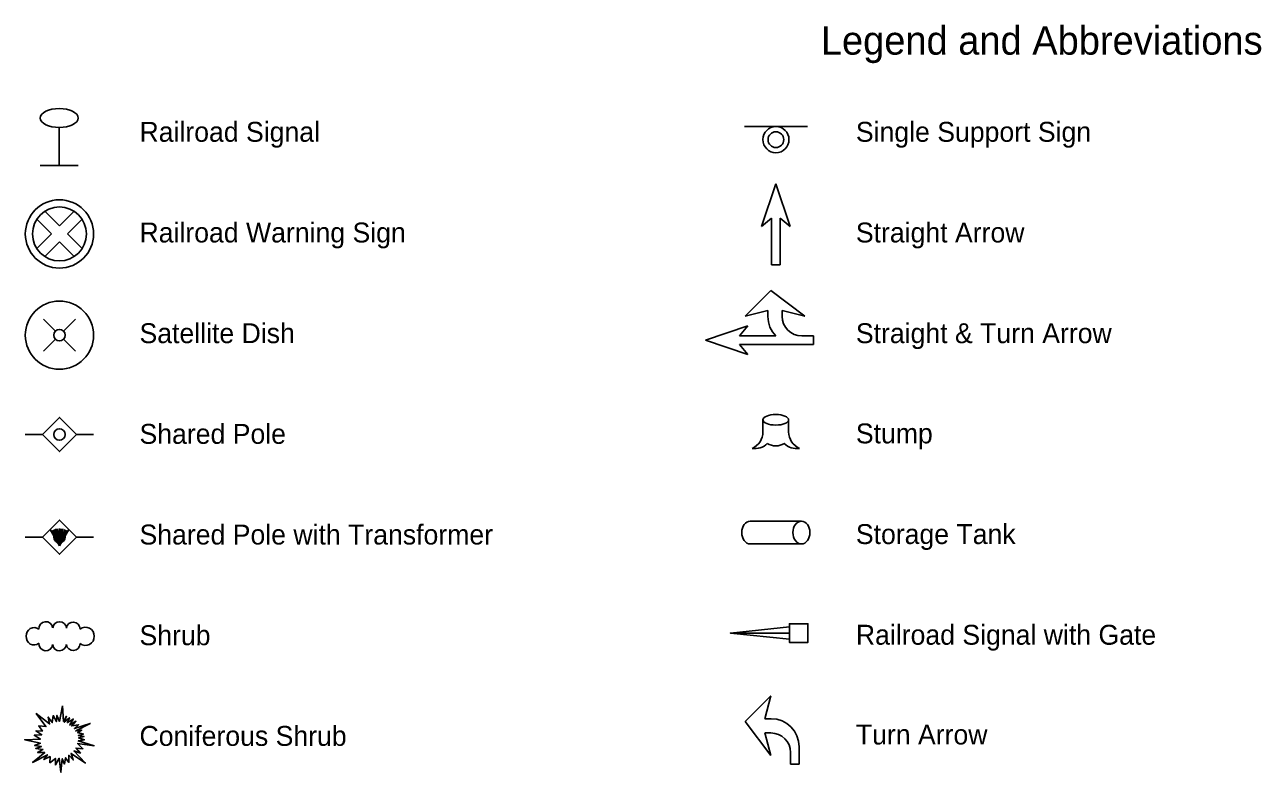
# Model space of a CAD drawing. Extents: x -371 to 730, y -9 to 425.
# Drawn here: x -68.8 to 40, y 358.9 to 424.6 of the extents above; entities that cross this region are included whole.
import ezdxf

# ---------------------------------------------------------------- set-up
doc = ezdxf.new("R2010")
doc.units = 0
for name, color, linetype in [('Pavemk_ep', 7, 'Continuous'), ('PolePower_ep', 7, 'Continuous'), ('RailroadMisc_ep', 7, 'Continuous'), ('SateDish_ep', 7, 'Continuous'), ('Shrub_ep', 7, 'Continuous'), ('SignSingle_ep', 7, 'Continuous'), ('Stump_ep', 7, 'Continuous'), ('TankStor_ep', 7, 'Continuous')]:
    doc.layers.add(name, color=color, linetype=linetype)

# ---------------------------------------------------------------- blocks, each defined once
blk = doc.blocks.new('STAROW')
at = {"layer": 'Pavemk_ep'}
for p, q in [((-1.67, -5), (0, 0)), ((0, 0), (1.67, -5)), ((-0.5, -4), (-1.67, -5)), ((-0.5, -9.5), (-0.5, -4)), ((0.5, -9.5), (0.5, -4)), ((1.67, -5), (0.5, -4)), ((-0.5, -9.5), (0.5, -9.5))]:
    blk.add_line(p, q, dxfattribs=at)
blk = doc.blocks.new('STATRN')
at = {"layer": 'Pavemk_ep'}
for p, q in [((-0.59, 5.33), (-3.59, 2.33)), ((-0.59, 5.33), (3.41, 2.33)), ((-3.59, 2.33), (-0.92, 3)), ((-0.92, 3), (-0.92, 2.28)), ((0.75, 3), (0.75, 2.3)), ((3.41, 2.33), (0.75, 3)), ((-3.26, 1.17), (-8.26, -0.5)), ((-4.26, 0), (-3.26, 1.17)), ((0, 0), (-4.26, 0)), ((4.41, 0), (3.04, 0)), ((4.41, 0), (4.41, -1)), ((-8.26, -0.5), (-3.26, -2.17)), ((4.41, -1), (-4.26, -1)), ((-3.26, -2.17), (-4.26, -1))]:
    blk.add_line(p, q, dxfattribs=at)
for centre, radius, end in [((2.36, 2.28), 3.28, 224.0462), ((3.04, 2.3), 2.3, 270)]:
    blk.add_arc(centre, radius, 180, end, dxfattribs=at)
blk = doc.blocks.new('TA')
at = {"layer": 'Pavemk_ep'}
for p, q in [((0, 0), (3, 3)), ((3, 3), (2.33, 0.33)), ((0, 0), (3, -4)), ((2.33, 0.33), (3.05175, 0.33)), ((2.33, -1.34), (3.03608, -1.34)), ((3, -4), (2.33, -1.34)), ((5.333, -5), (5.333, -3.63692)), ((6.333, -5), (6.333, -2.95125)), ((5.333, -5), (6.333, -5))]:
    blk.add_line(p, q, dxfattribs=at)
for centre, radius in [((3.05175, -2.95125), 3.28125), ((3.03608, -3.63692), 2.29692)]:
    blk.add_arc(centre, radius, 0, 90, dxfattribs=at)

msp = doc.modelspace()

# ---------------------------------------------------------------- linework, layer by layer
at = {"layer": 'PolePower_ep'}
for p, q in [((-68.71, 388.57), (-67.21, 388.57)), ((-64.21, 388.57), (-62.71, 388.57)), ((-68.71, 379.55), (-67.21, 379.55)), ((-65.71, 378.79), (-66.53, 380.23)), ((-66.32, 380.17), (-65.71, 378.79)), ((-66.17, 380.23), (-65.71, 378.79)), ((-66.02, 380.27), (-65.71, 378.79)), ((-65.87, 380.29), (-65.71, 378.79)), ((-65.71, 380.3), (-65.71, 378.79)), ((-65.55, 380.29), (-65.71, 378.79)), ((-65.4, 380.27), (-65.71, 378.79)), ((-64.88, 380.23), (-65.71, 378.79)), ((-65.24, 380.23), (-65.71, 378.79)), ((-65.1, 380.17), (-65.71, 378.79)), ((-64.21, 379.55), (-62.71, 379.55))]:
    msp.add_line(p, q, dxfattribs=at)
for points in [[(-67.21, 388.57), (-65.71, 387.07), (-64.21, 388.57), (-65.71, 390.07)], [(-67.21, 379.55), (-65.71, 378.05), (-64.21, 379.55), (-65.71, 381.05)]]:
    msp.add_lwpolyline(points, close=True, dxfattribs=at)
for centre in [(-65.71, 388.57), (-65.71, 379.55)]:
    msp.add_circle(centre, 0.5, dxfattribs=at)
at = {"layer": 'RailroadMisc_ep'}
for p, q in [((-65.73, 412.23), (-65.73, 415.56)), ((-67.4, 412.23), (-64.06, 412.23)), ((-65.71, 406.91), (-67, 408.2)), ((-64.42, 408.2), (-65.71, 406.91)), ((-66.42, 406.2), (-67.7, 407.49)), ((-63.71, 407.49), (-65, 406.2)), ((-66.42, 406.2), (-67.7, 404.92)), ((-63.71, 404.92), (-65, 406.2)), ((-65.71, 405.5), (-67, 404.21)), ((-64.42, 404.21), (-65.71, 405.5)), ((-6.71, 371.12), (-1.53, 371.12))]:
    msp.add_line(p, q, dxfattribs=at)
msp.add_lwpolyline([(-1.53, 371.66), (-1.53, 371.94), (0.11, 371.94), (0.11, 370.3), (-1.53, 370.3), (-1.53, 370.57), (-6.71, 371.12), (-1.53, 371.66), (-1.53, 370.57)], dxfattribs=at)
for radius in [3, 2.37]:
    msp.add_circle((-65.71, 406.2), radius, dxfattribs=at)
msp.add_ellipse((-65.73, 416.39), major_axis=(1.67, 0), ratio=0.5, dxfattribs=at)
at = {"layer": 'SateDish_ep'}
for p, q in [((-67.12, 398.72), (-66.06, 397.65)), ((-65.35, 397.65), (-64.29, 398.72)), ((-67.12, 395.89), (-66.06, 396.95)), ((-65.35, 396.95), (-64.29, 395.89))]:
    msp.add_line(p, q, dxfattribs=at)
for radius in [3, 0.5]:
    msp.add_circle((-65.71, 397.3), radius, dxfattribs=at)
at = {"layer": 'Shrub_ep'}
msp.add_lwpolyline([(-65.45, 364.73), (-65.34, 363.35), (-65.1, 363.8), (-65.29, 363.28), (-64.83, 363.67), (-65.01, 363.25), (-64.5, 363.56), (-64.8, 363.04), (-64.26, 363.36), (-64.63, 362.95), (-64.03, 363.05), (-64.39, 362.72), (-63, 363.17), (-64.27, 362.51), (-63.75, 362.59), (-64.12, 362.36), (-63.6, 362.24), (-64.05, 362.12), (-63.54, 362.03), (-64.03, 361.9), (-63.52, 361.73), (-64.06, 361.63), (-62.66, 361.21), (-64.12, 361.41), (-63.64, 360.95), (-64.25, 361), (-63.87, 360.57), (-64.44, 360.75), (-63.43, 359.69), (-64.68, 360.53), (-64.5, 359.97), (-64.89, 360.38), (-64.88, 359.74), (-65.17, 360.16), (-65.27, 359.6), (-65.46, 360.07), (-65.58, 358.88), (-65.73, 360.11), (-66.06, 359.53), (-66.06, 360.09), (-66.55, 359.71), (-66.53, 360.25), (-67.08, 359.99), (-66.77, 360.42), (-68.07, 359.74), (-67, 360.62), (-67.63, 360.61), (-67.17, 360.88), (-67.8, 360.98), (-67.29, 361.15), (-67.89, 361.23), (-67.39, 361.43), (-68.76, 361.73), (-67.38, 361.8), (-67.92, 362.13), (-67.26, 362.17), (-67.78, 362.51), (-67.2, 362.5), (-67.53, 362.96), (-66.9, 362.89), (-67.75, 364.04), (-66.58, 363.13), (-66.69, 363.73), (-66.34, 363.25), (-66.26, 363.86), (-65.97, 363.33), (-65.93, 363.88), (-65.71, 363.35)], close=True, dxfattribs=at)
for centre, radius, start, end in [((-66.91, 371.51), 0.606, 5.5993, 185.5993), ((-65.7, 371.51), 0.606, 4.3626, 174.4007), ((-64.5, 371.48), 0.606, 359.0898, 173.3908), ((-67.94, 370.9), 0.693, 52.1771, 185.6058), ((-67.94, 370.76), 0.693, 174.3942, 307.8229), ((-63.42, 370.87), 0.762, 357.0454, 127.8671), ((-63.42, 370.79), 0.762, 232.1329, 2.9546), ((-66.91, 370.16), 0.606, 174.4007, 354.4007), ((-65.7, 370.16), 0.606, 185.5994, 355.6374), ((-64.5, 370.18), 0.606, 186.6092, 0.9102), ((-63.89, 370.19), 4.547473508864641e-13, 0, 180)]:
    msp.add_arc(centre, radius, start, end, dxfattribs=at)
at = {"layer": 'SignSingle_ep'}
msp.add_line((-5.48, 415.65), (0.06, 415.65), dxfattribs=at)
for radius in [1.15, 0.692]:
    msp.add_circle((-2.71, 414.49), radius, dxfattribs=at)
at = {"layer": 'Stump_ep'}
for points in [[(-3.85, 389.86), (-3.85, 388.8)], [(-1.59, 388.8), (-1.59, 389.86)]]:
    msp.add_lwpolyline(points, dxfattribs=at)
for centre, radius, start, end in [((-5.43, 388.8), 1.58, 293.4251, 360), ((-0.01, 388.8), 1.58, 180, 246.5749), ((-4.56, 388.92), 1.59, 261.3796, 313.4136), ((-2.72, 389.1), 1.53, 240.6015, 299.3985), ((-0.88, 388.92), 1.59, 226.5864, 278.6204)]:
    msp.add_arc(centre, radius, start, end, dxfattribs=at)
msp.add_ellipse((-2.72, 389.86), major_axis=(1.13, 0), ratio=0.410203, dxfattribs=at)
at = {"layer": 'TankStor_ep'}
for p, q in [((-4.97, 380.95), (-0.47, 380.95)), ((-4.97, 378.95), (-0.47, 378.95))]:
    msp.add_line(p, q, dxfattribs=at)
msp.add_ellipse((-4.97, 379.95), major_axis=(0, -1), ratio=0.75, start_param=3.141593, end_param=6.283185, dxfattribs=at)
msp.add_ellipse((-0.47, 379.95), major_axis=(0, -1), ratio=0.75, dxfattribs=at)

# ---------------------------------------------------------------- block references
at = {"xscale": 0.75, "yscale": 0.75}
for name, p in [('STAROW', (-2.72, 410.6)), ('STATRN', (-2.72, 397.23)), ('TA', (-5.42, 363.34))]:
    msp.add_blockref(name, p, dxfattribs=at)

# ---------------------------------------------------------------- texts
for s, height, p in [('Legend and Abbreviations', 2.5, (1.24, 421.96)), ('Railroad Signal', 1.75, (-58.67, 414.3)), ('Single Support Sign', 1.75, (4.32, 414.3)), ('Railroad Warning Sign', 1.75, (-58.67, 405.45)), ('Straight Arrow', 1.75, (4.32, 405.45)), ('Satellite Dish', 1.75, (-58.67, 396.6)), ('Straight & Turn Arrow', 1.75, (4.32, 396.6)), ('Shared Pole', 1.75, (-58.67, 387.75)), ('Stump', 1.75, (4.32, 387.79)), ('Shared Pole with Transformer', 1.75, (-58.67, 378.9)), ('Storage Tank', 1.75, (4.32, 378.94)), ('Shrub', 1.75, (-58.67, 370.05)), ('Railroad Signal with Gate', 1.75, (4.32, 370.09)), ('Coniferous Shrub', 1.75, (-58.67, 361.2)), ('Turn Arrow', 1.75, (4.32, 361.32))]:
    msp.add_text(s, height=height).set_placement(p)

doc.saveas('drawing.dxf')
